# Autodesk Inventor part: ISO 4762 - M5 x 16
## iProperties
Library Location: C:\Program Files\Autodesk\Inventor 6\content
Library: local
SubLibrary: ISO
Family: 13
Member: 500
Member Major Revision: 1
Member Minor Revision: 1
Comments: To add or edit properties for Autodesk Inventor files, use iProperties.
Created: 2005-01
Part Number: ISO 4762 - M5 x 16
Vendor: Autodesk Inc.
Document SubType Name: Modeling
Designer: Flavien MARTY
Description: Vis cylindrique à six pans creux
Standard: ISO 4762 M5 x 16
Alert: To add or edit properties for Autodesk Inventor files, use iProperties.
Control State: 0
Master: False
Checked Out: False
Shininess: 64.0
Length Units: 11269
Angle Units: 11279
Time Units: 11290
Mass Units: 11283
Length Display Precision: 3
Angle Display Precision: 2
Compacted: True
EGR: 1
Density: 0.0
Volumn: 0.0
Area: 0.0
PropertySet Name: Model Information
Author: Flavien MARTY
Revision Number: 1
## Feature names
1. Corps [Revolution]
2. Fente [Extrusion]
3. Congé1 [Fillet]
4. Chanfrein1 [Chamfer]
